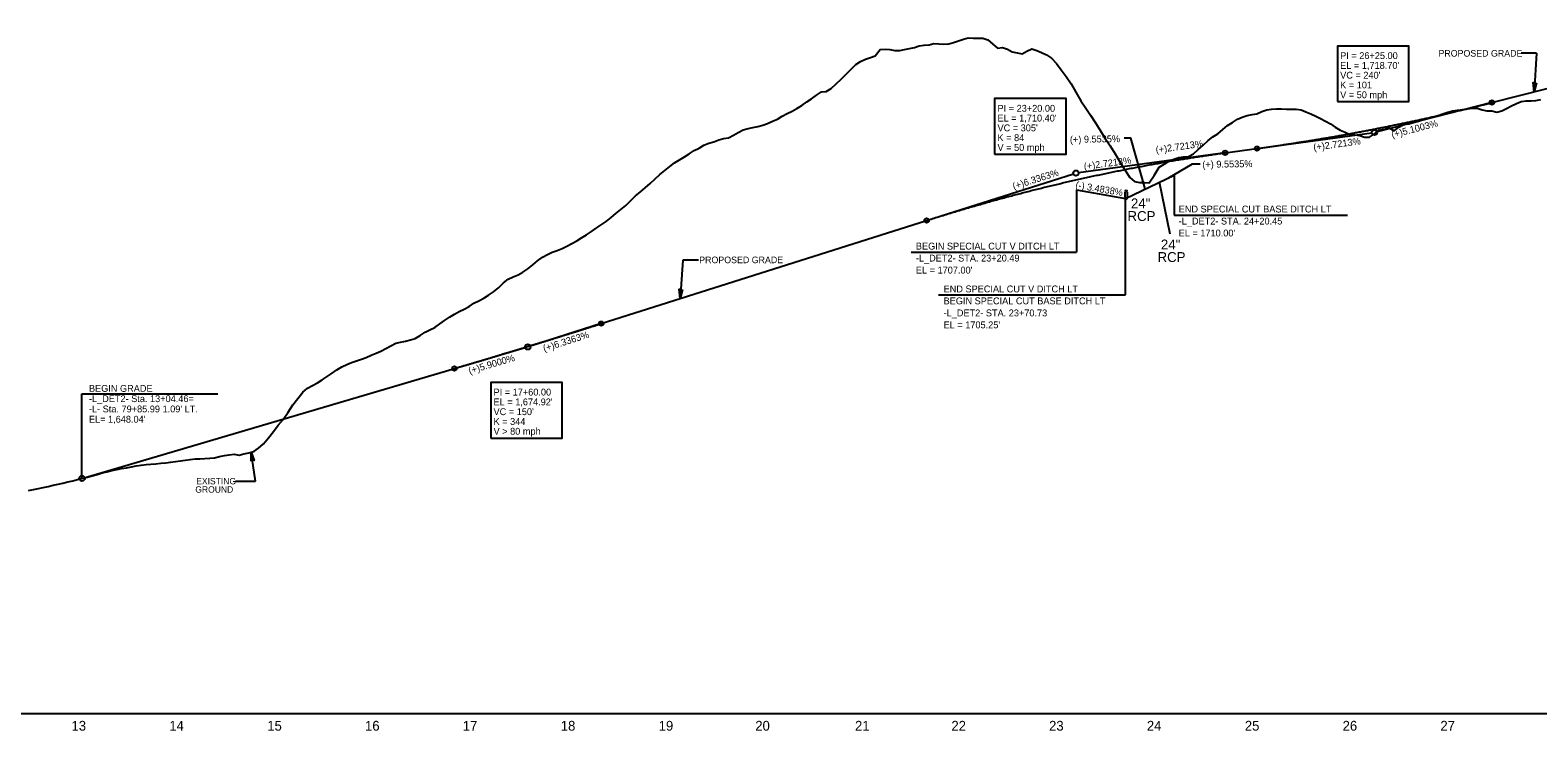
# Model space of a CAD drawing. Extents: x 498575 to 532350, y 405181 to 484585.
# Drawn here: x 506108 to 507649, y 437150 to 437865 of the extents above; entities that cross this region are included whole.
import ezdxf

# ---------------------------------------------------------------- set-up
doc = ezdxf.new("R2010")
doc.units = 0
for name, color, linetype in [('Exist Profile Cell', 7, 'Continuous'), ('Exist Vertical Profile Ground Line', 7, 'Continuous'), ('Exist Vertical Profile Horizontal Axis Label Major', 7, 'Continuous'), ('Prop Drainage Structure Pipe Welded Steel 54in Label', 7, 'Continuous'), ('Prop Grid Mask', 7, 'Continuous'), ('Prop PFL Text', 7, 'Continuous'), ('Prop Vertical Profile Curve Label', 7, 'Continuous'), ('Prop Vertical Profile Ditch Grade Left', 7, 'Continuous'), ('Prop Vertical Profile Ditch Grade Left Label', 7, 'Continuous'), ('Prop Vertical Profile Grade', 7, 'Continuous'), ('Prop Vertical Profile Grade Label', 7, 'Continuous'), ('Prop VPI Label', 7, 'Continuous'), ('Typical Terminator CELL', 7, 'Continuous')]:
    doc.layers.add(name, color=color, linetype=linetype)

# ---------------------------------------------------------------- blocks, each defined once
blk = doc.blocks.new('TERMINATOR')
at = {"layer": 'Typical Terminator CELL'}
blk.add_lwpolyline([(-0.469, 0.081), (0, 0), (-0.471, -0.083), (-0.411, 0)], close=True, dxfattribs=at)

msp = doc.modelspace()

# ---------------------------------------------------------------- linework, layer by layer
at = {"layer": 'Exist Profile Cell'}
msp.add_line((505856.7, 437167.2), (508769, 437167.2), dxfattribs=at)
at = {"layer": 'Exist Vertical Profile Ground Line'}
for points in [[(506856.7, 437768.3), (506861.7, 437769.9), (506866.7, 437772.1), (506871.7, 437774.4), (506876.7, 437777.4), (506881.7, 437780), (506886.7, 437782.5), (506891.7, 437785.1), (506896.7, 437788.4), (506901.7, 437792), (506906.7, 437795.2), (506911.7, 437798.8), (506916.7, 437802.1), (506921.7, 437802.4), (506926.7, 437805.8), (506931.7, 437810.5), (506936.7, 437815.2), (506941.7, 437819.9), (506946.7, 437824.9), (506951.7, 437830.1), (506956.7, 437833.2), (506961.7, 437835.6), (506966.7, 437837.3), (506971.7, 437839.1), (506976.7, 437845.3), (506981.7, 437845.8), (506986.7, 437845.6), (506991.7, 437844.5), (506996.7, 437844.3), (507001.7, 437845.4), (507006.7, 437846.5), (507011.7, 437847.6), (507016.7, 437849.1), (507021.7, 437849.8), (507026.7, 437850.4), (507031.7, 437851.7), (507036.7, 437851.3), (507041.7, 437850.8), (507046.7, 437851.2), (507051.7, 437852.7), (507056.7, 437854.3), (507061.7, 437855.9), (507066.7, 437857.5), (507071.7, 437857.2), (507076.7, 437857), (507081.7, 437856.9), (507086.7, 437855.5), (507091.7, 437850.8), (507096.7, 437846.7), (507101.7, 437847.4), (507106.7, 437845.8), (507111.7, 437843.2), (507116.7, 437842), (507121.7, 437841.1), (507126.7, 437843.9), (507131.7, 437846.3), (507136.7, 437844.6), (507141.7, 437842.5), (507146.7, 437840.1), (507151.7, 437836.5), (507156.7, 437831.3), (507161.7, 437824.7), (507166.7, 437817.8), (507171.7, 437810.4), (507176.7, 437801.9), (507181.7, 437793.1), (507186.7, 437785.5), (507191.7, 437778.4), (507196.7, 437770.4), (507201.7, 437762.4), (507206.7, 437754.6), (507211.7, 437746.9), (507216.7, 437739), (507221.7, 437730.8), (507226.7, 437722.6), (507231.7, 437714.8), (507236.7, 437710.8), (507241.7, 437709.6), (507246.7, 437709.5), (507251.7, 437709.4), (507256.7, 437716.7), (507261.7, 437725.4), (507266.7, 437728.4), (507271.7, 437731.5), (507276.7, 437733.6), (507281.7, 437735.1), (507286.7, 437735.9), (507291.7, 437736.3), (507296.7, 437739), (507301.7, 437743.3), (507306.7, 437747.8), (507311.7, 437752.6), (507316.7, 437756.1), (507321.7, 437759.4), (507326.7, 437763.8), (507331.7, 437767.9), (507336.7, 437771), (507341.7, 437774.2), (507346.7, 437776.3), (507351.7, 437778.2), (507356.7, 437779)], [(507356.7, 437779), (507361.7, 437779.9), (507366.7, 437782.1), (507371.7, 437783.8), (507376.7, 437784.6), (507381.7, 437784.7), (507386.7, 437784.7), (507391.7, 437784.5), (507396.7, 437784.5), (507401.7, 437784.5), (507406.7, 437783.9), (507411.7, 437781.9), (507416.7, 437779.9), (507421.7, 437777.5), (507426.7, 437775), (507431.7, 437772.4), (507436.7, 437769.4), (507441.7, 437766.1), (507446.7, 437763), (507451.7, 437760.9), (507456.7, 437758.8), (507461.7, 437758.2), (507466.7, 437757.5), (507471.7, 437755.8), (507476.7, 437755.8), (507481.7, 437759.3), (507486.7, 437762.9), (507491.7, 437764.1), (507496.7, 437765.4), (507501.7, 437762.3), (507506.7, 437766.2), (507511.7, 437768.7), (507516.7, 437769.7), (507521.7, 437770.8), (507526.7, 437772.4), (507531.7, 437773.8), (507536.7, 437775.2), (507541.7, 437776.6), (507546.7, 437778.1), (507551.7, 437779.9), (507556.7, 437781.5), (507561.7, 437782.8), (507566.7, 437783.5), (507571.7, 437784.1), (507576.7, 437784.9), (507581.7, 437785.6), (507586.7, 437785.4), (507591.7, 437784), (507596.7, 437782.8), (507601.7, 437782.7), (507606.7, 437781.5), (507611.7, 437782.9), (507616.7, 437785.3), (507621.7, 437787.8), (507626.7, 437790.3), (507631.7, 437792.2), (507636.7, 437792.9), (507641.7, 437793.1), (507646.7, 437793.4), (507651.7, 437794.3)], [(506356.7, 437455.2), (506361.7, 437461.9), (506366.7, 437467.5), (506371.7, 437475.1), (506376.7, 437482.4), (506381.7, 437489.1), (506386.7, 437495.3), (506391.7, 437499.4), (506396.7, 437502.3), (506401.7, 437505), (506406.7, 437508), (506411.7, 437511.6), (506416.7, 437515), (506421.7, 437518.3), (506426.7, 437521.2), (506431.7, 437523.6), (506436.7, 437525.6), (506441.7, 437527.6), (506446.7, 437529.3), (506451.7, 437531), (506456.7, 437533.1), (506461.7, 437535.2), (506466.7, 437537.5), (506471.7, 437540.1), (506476.7, 437542.9), (506481.7, 437545.6), (506486.7, 437546.5), (506491.7, 437547.4), (506496.7, 437548.8), (506501.7, 437550.3), (506506.7, 437553.4), (506511.7, 437556.6), (506516.7, 437559), (506521.7, 437561.5), (506526.7, 437565.1), (506531.7, 437568.8), (506536.7, 437572.1), (506541.7, 437575.2), (506546.7, 437577.8), (506551.7, 437580.4), (506556.7, 437583.1), (506561.7, 437586.2), (506566.7, 437588.9), (506571.7, 437591.3), (506576.7, 437594.6), (506581.7, 437598.1), (506586.7, 437602), (506591.7, 437607), (506596.7, 437610.8), (506601.7, 437613.1), (506606.7, 437615.2), (506611.7, 437618), (506616.7, 437621.3), (506621.7, 437625.5), (506626.7, 437629.6), (506631.7, 437633.5), (506636.7, 437636.1), (506641.7, 437638.6), (506646.7, 437640.3), (506651.7, 437642.3), (506656.7, 437644.7), (506661.7, 437647.4), (506666.7, 437650.2), (506671.7, 437653.2), (506676.7, 437656.2), (506681.7, 437659.5), (506686.7, 437662.8), (506691.7, 437666.4), (506696.7, 437669.9), (506701.7, 437673.9), (506706.7, 437677.9), (506711.7, 437681.9), (506716.7, 437686), (506721.7, 437690.9), (506726.7, 437696), (506731.7, 437700), (506736.7, 437704.2), (506741.7, 437708.5), (506746.7, 437713.2), (506751.7, 437717.7), (506756.7, 437721.9), (506761.7, 437725.8), (506766.7, 437729.7), (506771.7, 437732.8), (506776.7, 437735.9), (506781.7, 437739), (506786.7, 437742.2), (506791.7, 437744.8), (506796.7, 437747.7), (506801.7, 437749.8), (506806.7, 437751.2), (506811.7, 437753.1), (506816.7, 437754.5), (506821.7, 437755.4), (506826.7, 437758.1), (506831.7, 437760.8), (506836.7, 437763.3), (506841.7, 437764.8), (506846.7, 437765.7), (506851.7, 437766.9), (506856.7, 437768.3)], [(506106.7, 437395), (506111.7, 437396), (506116.7, 437397), (506121.7, 437398.1), (506126.7, 437399.2), (506131.7, 437400.3), (506136.7, 437401.4), (506141.7, 437402.6), (506146.7, 437403.8), (506151.7, 437405), (506156.7, 437406.2), (506161.7, 437407.5), (506166.7, 437408.8), (506171.7, 437410.1), (506176.7, 437411.5), (506181.7, 437412.9), (506186.7, 437414.2), (506191.7, 437415.5), (506196.7, 437416.5), (506201.7, 437417.4), (506206.7, 437418.3), (506211.7, 437419.2), (506216.7, 437420.1), (506221.7, 437421), (506226.7, 437421.4), (506231.7, 437421.8), (506236.7, 437422.3), (506241.7, 437422.9), (506246.7, 437423.4), (506251.7, 437424.1), (506256.7, 437424.7), (506261.7, 437425.3), (506266.7, 437426), (506271.7, 437426.7), (506276.7, 437427.2), (506281.7, 437427.5), (506286.7, 437427.7), (506291.7, 437428), (506296.7, 437428.3), (506301.7, 437429.7), (506306.7, 437430.6), (506311.7, 437431.5), (506316.7, 437432), (506321.7, 437431.2), (506326.7, 437432.6), (506331.7, 437433.6), (506336.7, 437434.9), (506341.7, 437438.4), (506346.7, 437442.8), (506351.7, 437448.7), (506356.7, 437455.2)]]:
    msp.add_lwpolyline(points, dxfattribs=at)
at = {"layer": 'Prop Drainage Structure Pipe Welded Steel 54in Label'}
msp.add_line((507273, 437656.7), (507262.1, 437710), dxfattribs=at)
msp.add_ellipse((507228, 437697.2), major_axis=(0, 5), ratio=0.2, dxfattribs=at)
at = {"layer": 'Prop Grid Mask'}
for points in [[(507443.8, 437792.2), (507516.8, 437792.2), (507516.8, 437849), (507443.8, 437849)], [(507093.6, 437738.5), (507166.6, 437738.5), (507166.6, 437795.3), (507093.6, 437795.3)], [(506578.8, 437448.6), (506651.8, 437448.6), (506651.8, 437505.3), (506578.8, 437505.3)]]:
    msp.add_lwpolyline(points, close=True, dxfattribs=at)
at = {"layer": 'Prop PFL Text'}
for p, q in [((507647.4, 437841.6), (507631.5, 437841.6)), ((507647.4, 437841.6), (507644.9, 437802.3)), ((506775, 437630.4), (506772.5, 437591.1)), ((506791, 437630.4), (506775, 437630.4)), ((506338.4, 437404.6), (506334.2, 437434.2)), ((506318, 437404.6), (506338.4, 437404.6))]:
    msp.add_line(p, q, dxfattribs=at)
msp.add_lwpolyline([(506334, 437425.1), (506334.2, 437434.2), (506337.1, 437425.5), (506335.3, 437426.4)], close=True, dxfattribs=at)
at = {"layer": 'Prop Vertical Profile Curve Label'}
for centre in [(507601.7, 437791.3), (507329.2, 437739.9), (507361.7, 437744.3), (507024.2, 437670.8), (506691.7, 437565.5), (506541.7, 437519.6)]:
    msp.add_circle(centre, 2.25, dxfattribs=at)
at = {"layer": 'Prop Vertical Profile Ditch Grade Left'}
msp.add_lwpolyline([(507177.2, 437702.2), (507227.5, 437693.4), (507277.2, 437717.2)], dxfattribs=at)
at = {"layer": 'Prop Vertical Profile Ditch Grade Left Label'}
for p, q in [((507277.2, 437717.2), (507277.2, 437676.3)), ((507177.2, 437702.2), (507177.2, 437638.6)), ((507227.5, 437594.8), (507227.5, 437693.4)), ((507277.2, 437676.3), (507454.2, 437676.3)), ((507008.5, 437638.6), (507177.2, 437638.6)), ((507036.2, 437594.8), (507227.5, 437594.8))]:
    msp.add_line(p, q, dxfattribs=at)
for points in [[(507247.6, 437703), (507232.9, 437755), (507226.1, 437755)], [(507270.9, 437714.2), (507295.7, 437728.7), (507303.8, 437728.7)]]:
    msp.add_lwpolyline(points, dxfattribs=at)
at = {"layer": 'Prop Vertical Profile Grade'}
for p, q in [((507601.7, 437791.3), (507891.7, 437865.2)), ((507329.2, 437739.9), (507361.7, 437744.3)), ((506691.7, 437565.5), (507024.2, 437670.8)), ((506161.2, 437407.4), (506541.7, 437519.6))]:
    msp.add_line(p, q, dxfattribs=at)
for points in [[(507361.7, 437744.3), (507366.5, 437745), (507371.3, 437745.7), (507376.1, 437746.3), (507380.9, 437747), (507385.7, 437747.7), (507390.5, 437748.5), (507395.3, 437749.2), (507400.1, 437749.9), (507404.9, 437750.7), (507409.7, 437751.4), (507414.5, 437752.2), (507419.3, 437753), (507424.1, 437753.8), (507428.9, 437754.6), (507433.7, 437755.4), (507438.5, 437756.2), (507443.3, 437757.1), (507448.1, 437757.9), (507452.9, 437758.8), (507457.7, 437759.7), (507462.5, 437760.6), (507467.3, 437761.5), (507472.1, 437762.4), (507476.9, 437763.3), (507481.7, 437764.2), (507486.5, 437765.2), (507491.3, 437766.1), (507496.1, 437767.1), (507500.9, 437768.1), (507505.7, 437769.1), (507510.5, 437770.1), (507515.3, 437771.1), (507520.1, 437772.1), (507524.9, 437773.1), (507529.7, 437774.2), (507534.5, 437775.2), (507539.3, 437776.3), (507544.1, 437777.4), (507548.9, 437778.5), (507553.7, 437779.6), (507558.5, 437780.7), (507563.3, 437781.8), (507568.1, 437783), (507572.9, 437784.1), (507577.7, 437785.3), (507582.5, 437786.5), (507587.3, 437787.6), (507592.1, 437788.8), (507596.9, 437790), (507601.7, 437791.3)], [(507024.2, 437670.8), (507030.3, 437672.8), (507036.4, 437674.7), (507042.5, 437676.5), (507048.6, 437678.4), (507054.7, 437680.2), (507060.8, 437682), (507066.9, 437683.8), (507073, 437685.6), (507079.1, 437687.3), (507085.2, 437689.1), (507091.3, 437690.8), (507097.4, 437692.5), (507103.5, 437694.1), (507109.6, 437695.7), (507115.7, 437697.4), (507121.8, 437698.9), (507127.9, 437700.5), (507134, 437702.1), (507140.1, 437703.6), (507146.2, 437705.1), (507152.3, 437706.6), (507158.4, 437708), (507164.5, 437709.5), (507170.6, 437710.9), (507176.7, 437712.3), (507182.8, 437713.6), (507188.9, 437715), (507195, 437716.3), (507201.1, 437717.6), (507207.2, 437718.9), (507213.3, 437720.2), (507219.4, 437721.4), (507225.5, 437722.6), (507231.6, 437723.8), (507237.7, 437725), (507243.8, 437726.1), (507249.9, 437727.3), (507256, 437728.4), (507262.1, 437729.4), (507268.2, 437730.5), (507274.3, 437731.6), (507280.4, 437732.6), (507286.5, 437733.6), (507292.6, 437734.5), (507298.7, 437735.5), (507304.8, 437736.4), (507310.9, 437737.3), (507317, 437738.2), (507323.1, 437739.1), (507329.2, 437739.9)], [(506541.7, 437519.6), (506544.7, 437520.5), (506547.7, 437521.4), (506550.7, 437522.3), (506553.7, 437523.2), (506556.7, 437524.1), (506559.7, 437525), (506562.7, 437525.9), (506565.7, 437526.7), (506568.7, 437527.6), (506571.7, 437528.5), (506574.7, 437529.4), (506577.7, 437530.3), (506580.7, 437531.2), (506583.7, 437532.1), (506586.7, 437533), (506589.7, 437534), (506592.7, 437534.9), (506595.7, 437535.8), (506598.7, 437536.7), (506601.7, 437537.6), (506604.7, 437538.5), (506607.7, 437539.4), (506610.7, 437540.3), (506613.7, 437541.2), (506616.7, 437542.2), (506619.7, 437543.1), (506622.7, 437544), (506625.7, 437544.9), (506628.7, 437545.8), (506631.7, 437546.8), (506634.7, 437547.7), (506637.7, 437548.6), (506640.7, 437549.5), (506643.7, 437550.5), (506646.7, 437551.4), (506649.7, 437552.3), (506652.7, 437553.3), (506655.7, 437554.2), (506658.7, 437555.1), (506661.7, 437556.1), (506664.7, 437557), (506667.7, 437557.9), (506670.7, 437558.9), (506673.7, 437559.8), (506676.7, 437560.8), (506679.7, 437561.7), (506682.7, 437562.7), (506685.7, 437563.6), (506688.7, 437564.6), (506691.7, 437565.5)]]:
    msp.add_spline(points, degree=3, dxfattribs=at)
at = {"layer": 'Prop VPI Label'}
for p, q in [((507601.7, 437791.3), (507484.4, 437761.3)), ((507361.7, 437744.3), (507479, 437760.3)), ((507329.2, 437739.9), (507179.5, 437719.5)), ((507024.2, 437670.8), (507174.1, 437718.3)), ((506691.7, 437565.5), (506619.4, 437542.6)), ((506541.7, 437519.6), (506614.1, 437541)), ((506161.2, 437407.4), (506161.2, 437493.8)), ((506161.2, 437493.8), (506269.5, 437493.8)), ((506161.2, 437493.8), (506300, 437493.8))]:
    msp.add_line(p, q, dxfattribs=at)
for centre in [(507481.7, 437760.7), (507176.7, 437719.2), (506616.7, 437541.7), (506161.2, 437407.4)]:
    msp.add_circle(centre, 2.75, dxfattribs=at)

# ---------------------------------------------------------------- block references
at = {"layer": 'Prop PFL Text', "xscale": 20, "yscale": 19.999999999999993, "rotation": -93.70508386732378}
for p in [(507644.9, 437802.3), (506772.5, 437591.1)]:
    msp.add_blockref('TERMINATOR', p, dxfattribs=at)

# ---------------------------------------------------------------- texts
at = {"layer": 'Exist Vertical Profile Horizontal Axis Label Major'}
for s, p in [('13', (506150.5, 437149.7)), ('14', (506250.4, 437149.7)), ('15', (506350.5, 437149.7)), ('16', (506450.4, 437149.7)), ('17', (506550.3, 437149.7)), ('18', (506650.4, 437149.7)), ('19', (506750.4, 437149.7)), ('20', (506849.1, 437149.7)), ('21', (506951, 437149.7)), ('22', (507049.5, 437149.7)), ('23', (507149.3, 437149.7)), ('24', (507249.2, 437149.7)), ('25', (507349.3, 437149.7)), ('26', (507449.2, 437149.7)), ('27', (507549.1, 437149.7))]:
    msp.add_text(s, height=10, dxfattribs=at).set_placement(p)
at = {"layer": 'Prop Drainage Structure Pipe Welded Steel 54in Label'}
for s, p in [('RCP', (507229.4, 437670.3)), ('24" ', (507232.9, 437683.2)), ('24" ', (507263.5, 437641.2)), ('RCP', (507260.1, 437628.4))]:
    msp.add_text(s, height=10.12, dxfattribs=at).set_placement(p)
at = {"layer": 'Prop PFL Text'}
for s, height, p in [('PROPOSED GRADE', 6.75, (507547.1, 437838.2)), ('PROPOSED GRADE', 6.75, (506791.8, 437627.2)), ('EXISTING', 6.52, (506277.9, 437401.3)), ('GROUND', 6.52, (506277, 437392.8))]:
    msp.add_text(s, height=height, dxfattribs=at).set_placement(p)
at = {"layer": 'Prop Vertical Profile Curve Label'}
for s, p in [("VC = 240'", (507446.7, 437815.7)), ('K = 101', (507446.7, 437805.7)), ('V = 50 mph', (507446.7, 437795.7)), ("VC = 305'", (507096.6, 437761.9)), ('K = 84', (507096.6, 437751.9)), ('V = 50 mph', (507096.6, 437741.9)), ("VC = 150'", (506581.7, 437472)), ('K = 344', (506581.7, 437462)), ('V > 80 mph', (506581.7, 437452))]:
    msp.add_text(s, height=7, dxfattribs=at).set_placement(p)
at = {"layer": 'Prop Vertical Profile Ditch Grade Left Label'}
for s, rotation, p in [('(+) 9.5535%', 0.8384, (507170.6, 437750.1)), ('(+) 9.5535%', 0.8384, (507305.9, 437724.6)), ('(-) 3.4838%', 350.382, (507175.8, 437703.9)), ('END SPECIAL CUT BASE DITCH LT', 360, (507281.7, 437679)), ('-L_DET2- STA. 24+20.45', 360, (507281.7, 437666.7)), ("EL = 1710.00'", 360, (507281.7, 437654.5)), ('-L_DET2- STA. 23+20.49', 360, (507013.2, 437628.9)), ('BEGIN SPECIAL CUT V DITCH LT', 360, (507013.2, 437641.1)), ("EL = 1707.00'", 360, (507013.2, 437616.6)), ('END SPECIAL CUT V DITCH LT', 360, (507041.5, 437597.4)), ('BEGIN SPECIAL CUT BASE DITCH LT', 360, (507041.5, 437585.2)), ('-L_DET2- STA. 23+70.73', 360, (507041.5, 437572.9)), ("EL = 1705.25'", 360, (507041.5, 437560.7))]:
    msp.add_text(s, height=7, rotation=rotation, dxfattribs=at).set_placement(p)
at = {"layer": 'Prop Vertical Profile Grade Label'}
for s, rotation, p in [('(+)5.1003%', 14.3062, (507499.9, 437755)), ('(+)2.7213%', 7.7484, (507258.7, 437739.5)), ('(+)2.7213%', 7.7484, (507419.8, 437742.1)), ('(+)2.7213%', 7.7484, (507185.3, 437722.5)), ('(+)6.3363%', 17.5789, (507113.3, 437702.2)), ('(+)6.3363%', 17.5789, (506633.5, 437536.6)), ('(+)5.9000%', 16.4361, (506557.3, 437513.8))]:
    msp.add_text(s, height=7, rotation=rotation, dxfattribs=at).set_placement(p)
at = {"layer": 'Prop VPI Label'}
for s, p in [('PI = 26+25.00', (507446.7, 437835.7)), ("EL = 1,718.70'", (507446.7, 437825.7)), ('PI = 23+20.00', (507096.6, 437781.9)), ("EL = 1,710.40'", (507096.6, 437771.9)), ('BEGIN GRADE', (506168.3, 437495.8)), ('PI = 17+60.00', (506581.7, 437492)), ('-L_DET2- Sta. 13+04.46=', (506168.3, 437485.3)), ("-L- Sta. 79+85.99 1.09' LT.", (506168.3, 437474.8)), ("EL = 1,674.92'", (506581.7, 437482)), ("EL= 1,648.04'", (506168.3, 437464.3))]:
    msp.add_text(s, height=7, dxfattribs=at).set_placement(p)

doc.saveas('drawing.dxf')
